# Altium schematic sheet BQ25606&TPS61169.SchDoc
size A3
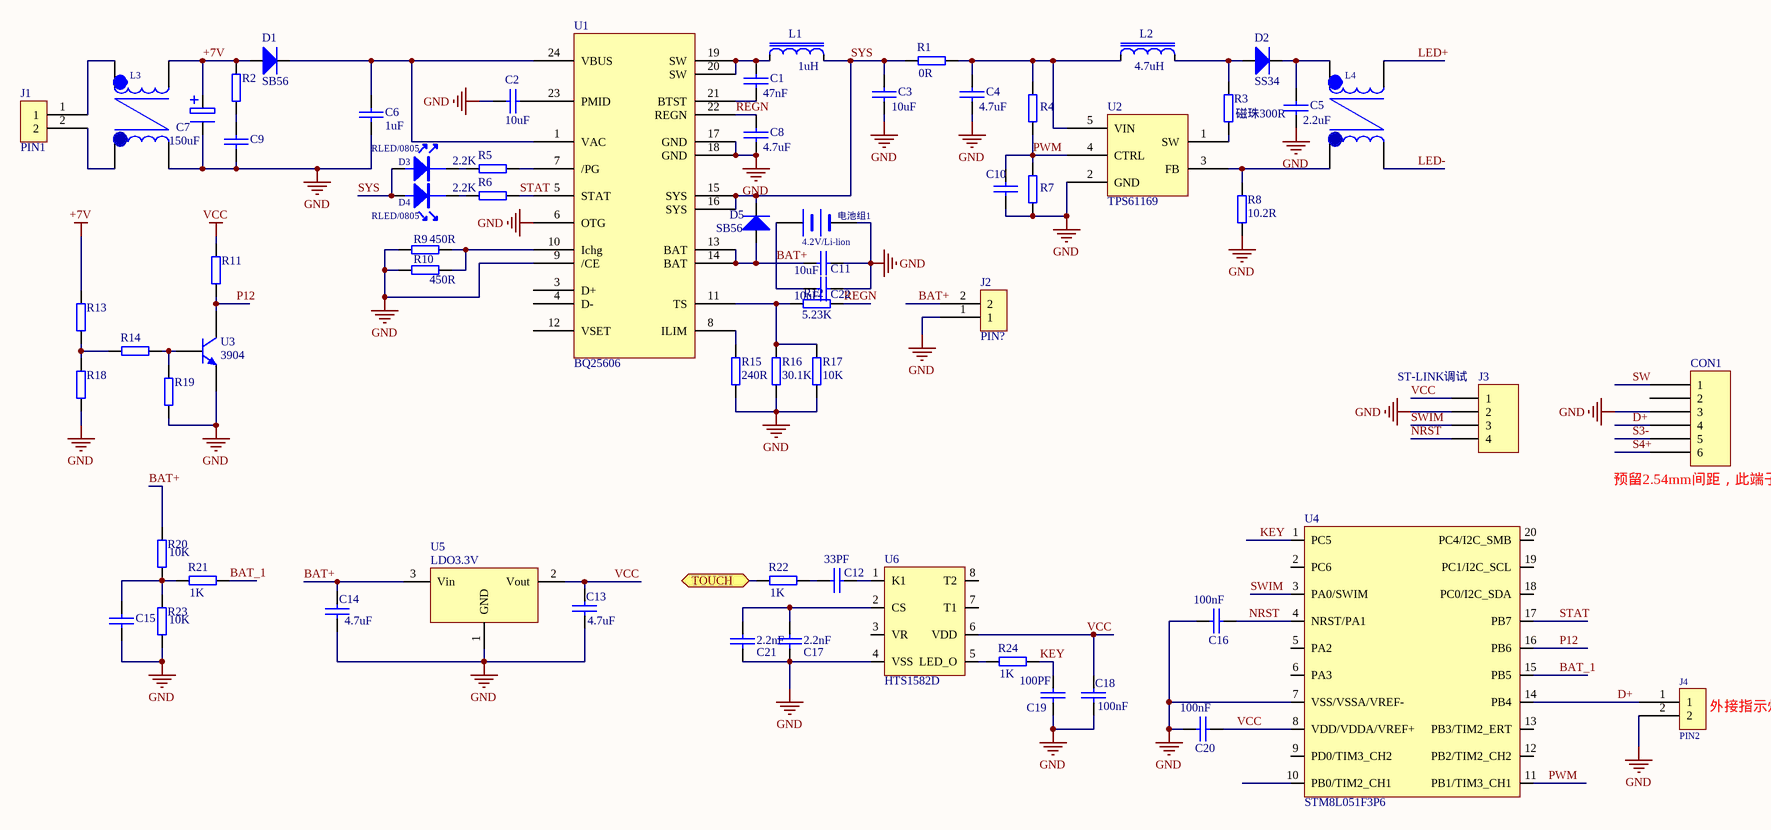
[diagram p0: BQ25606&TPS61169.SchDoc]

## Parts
C1  47nF  [C/S-0805(T)]
C2  10uF  [C/S-1206(T)]
C3  10uF  [C/S-1206(T)]
C4  4.7uF  [C/S-1206(T)]
C5  2.2uF  [C/S-1206(T)]
C6  1uF  [C/S-0805(T)]
C7  150uF  [CD   6.3*12   P2.5（多）]
C8  4.7uF  [C/S-0805(T)]
C9  (no value)  [C/S-1206(T)]
C10  (no value)  [C/S-0805(T)]
C11  10uF  [C/S-1206(T)]
C12  33PF  [C/S-0805(T)]
C13  4.7uF  [C/S-0805(T)]
C14  4.7uF  [C/S-0805(T)]
C15  (no value)  [C/S-0805(T)]
C16  100nF  [C/S-0805(T)]
C17  2.2nF  [C/S-1206(T)]
C18  100nF  [C/S-1206(T)]
C19  100PF  [C/S-0805(T)]
C20  100nF  [C/S-0805(T)]
C21  2.2nF  [C/S-1206(T)]
C22  10uF  [C/S-1206(T)]
CON1  (no value)
D1  SB56  [D SMB(T)]
D2  SS34  [D SMA(T)]
D3  RLED/0805  [D/S 0603发光二极管（T)]
D4  RLED/0805  [D/S 0603发光二极管（T)]
D5  SB56  [D SMB(T)]
J1  PIN1  [SW/D 2PIN 2.5]
J2  PIN?  [SW/D 2PIN 2.5]
J3  ST-LINK调试  [SW/D  公端子 G2.54 4P 直插 (多)]
J4  PIN2  [SW/D 2PIN 2.5]
L1  1uH  [L/S SWPA6028S(T)]
L2  4.7uH  [L/S SWPA6028S(T)]
L3  (no value)  [L/D-底座磁环H10*6*5（多）]
L4  (no value)  [L/D-底座磁环H10*6*5（多）]
R1  0R  [R/S-0805(T)]
R2  (no value)  [R/S-1206(T)]
R3  磁珠300R  [L/S 磁珠3216(T)]
R4  (no value)  [R/S-0805(T)]
R5  2.2K  [R/S-0805(T)]
R6  2.2K  [R/S-0805(T)]
R7  (no value)  [R/S-0805(T)]
R8  10.2R  [R/S-1206(T)]
R9  450R  [R/S-1206(T)]
R10  450R  [R/S-1206(T)]
R11  (no value)  [R/S-0805(T)]
R12  5.23K  [R/S-0805(T)]
R13  (no value)  [R/S-0805(T)]
R14  (no value)  [R/S-0805(T)]
R15  240R  [R/S-1206(T)]
R16  30.1K  [R/S-0805(T)]
R17  10K  [R/S-0805(T)]
R18  (no value)  [R/S-0805(T)]
R19  (no value)  [R/S-0805(T)]
R20  10K  [R/S-0805(T)]
R21  1K  [R/S-0805(T)]
R22  1K  [R/S-0805(T)]
R23  10K  [R/S-0805(T)]
R24  1K  [R/S-0805(T)]
U1  BQ25606  [BQ25606]
U2  TPS61169  [TPS61169]
U3  3904  [U IC   SOT-23   (T)]
U4  STM8L051F3P6  [U IC   TSSOP 20 (T)-验证]
U5  LDO3.3V  [U IC   SOT-23   (T)]
U6  HTS1582D  [U IC   SO8/SO-8/SOP-8/SO-8C/SO-8N/SO-8EP/SOIC-8 (T)]
电池组1  4.2V/Li-lion

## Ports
TOUCH

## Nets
+7V: C7.1 D1.A L3.4 R2.2 R13.1
GND: C2.2 C3.1 C4.1 C5.1 C6.2 C7.2 C8.1 C9.2 C10.1 C11.2 C13.2 C14.2 C15.2 C16.1 C17.2 C18.2 C19.2 C20.1 C21.2 C22.2 CON1.?3(3) J2.1 J3.2 J4.2 L3.3 R7.2 R8.2 R9.1 R10.1 R15.2 R16.2 R17.2 R18.2 R19.2 R23.2 U1.6(OTG) U1.9(/CE) U1.17(GND) U1.18(GND) U2.2(GND) U3.1(E) U4.7(VSS/VSSA/VREF-) U5.1(GND) U6.4(VSS) 电池组1.2(-)
VCC: C13.1 C18.1 C20.2 J3.1 R11.1 U4.8(VDD/VDDA/VREF+) U5.2(Vout) U6.6(VDD)
BAT+: C11.1 C14.1 C22.1 D5.A J2.2 R20.1 U1.13(BAT) U1.14(BAT) U5.3(Vin) 电池组1.1(+)
BAT_1: R21.1 U4.15(PB5)
D+: CON1.?4(4) J4.1 U4.14(PB4)
KEY: C19.1 R24.1 U4.1(PC5)
LED+: L4.4
LED-: L4.3
NRST: C16.2 J3.4 U4.4(NRST/PA1)
P12: R11.2 U3.3(C) U4.16(PB6)
PWM: C10.2 R4.2 R7.1 U2.4(CTRL) U4.11(PB1/TIM3_CH1)
REGN: C8.2 R12.1 U1.22(REGN)
S3-: CON1.?5(5)
S4+: CON1.?6(6)
STAT: R6.2 U1.5(STAT) U4.17(PB7)
SW: CON1.?1(1)
SWIM: J3.3 U4.3(PA0/SWIM)
SYS: C3.2 D3.A D4.A D5.K L1.2 R1.2 U1.15(SYS) U1.16(SYS)
TOUCH: R22.2 ; port TOUCH
NetC1_1: C1.1 U1.21(BTST)
NetC1_2: C1.2 L1.1 U1.19(SW) U1.20(SW)
NetC2_1: C2.1 U1.23(PMID)
NetC4_2: C4.2 L2.1 R1.1 R4.1 U2.5(VIN)
NetC5_2: C5.2 D2.K L4.2
NetC6_1: C6.1 D1.K U1.1(VAC) U1.24(VBUS)
NetC9_1: C9.1 R2.1
NetC12_1: C12.1 U6.1(K1)
NetC12_2: C12.2 R22.1
NetC15_1: C15.1 R20.2 R21.2 R23.1
NetC17_1: C17.1 C21.1 U6.2(CS)
NetD2_A: D2.A L2.2 R3.1
NetD3_K: D3.K R5.1
NetD4_K: D4.K R6.1
NetJ1_1: J1.1 L3.2
NetJ1_2: J1.2 L3.1
NetL4_1: L4.1 R8.1 U2.3(FB)
NetR3_2: R3.2 U2.1(SW)
NetR5_2: R5.2 U1.7(/PG)
NetR9_2: R9.2 R10.2 U1.10(Ichg)
NetR12_2: R12.2 R16.1 R17.1 U1.11(TS)
NetR13_2: R13.2 R14.2 R18.1
NetR14_1: R14.1 R19.1 U3.2(B)
NetR15_1: R15.1 U1.8(ILIM)
NetR24_2: R24.2 U6.5(LED_O)

Not connected (* = marked no-connect by the designer): CON1 ?2(2); U1 3(D+) 4(D-) 12(VSET); U4 2(PC6) 5(PA2) 6(PA3) 9(PD0/TIM3_CH2) 10(PB0/TIM2_CH1) 12(PB2/TIM2_CH2) 13(PB3/TIM2_ERT) 18(PC0/I2C_SDA) 19(PC1/I2C_SCL) 20(PC4/I2C_SMB); U6 3(VR) 7(T1) 8(T2)

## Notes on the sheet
- (near CON1) 预留2.54mm间距，此端子已固定
- (near J4) 外接指示灯

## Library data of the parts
C1-C6 C8-C22 = C: Capacitor
C7 = C-E
CON1 = CON5
D1 D2 D5 = D-GR: Diode
D3 D4 = LED
J1 J2 = PIN2
J3 = Header 4: Header, 4-Pin
L1 L2 = L-3
L3 L4 = TRANS1
R1-R24 = R
U3 = 2N3904: NPN General Purpose Amplifier
U5 = MCP1700
电池组1 = BATTERY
